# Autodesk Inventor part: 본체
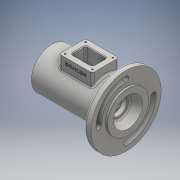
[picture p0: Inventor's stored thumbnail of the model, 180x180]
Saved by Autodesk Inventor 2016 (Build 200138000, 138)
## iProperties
Created: 2017-05
Part Number: 본체
Material: 일반
Document SubType Name: Modeling
Designer: USER
Density: 1 g/cm^3
Appearance: 기본값
Author: USER
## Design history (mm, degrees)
sketch "스케치1"
  geometry: L1 (0, 0)-(0, 31); L2 (0, 31)-(102, 31); L3 (102, 31)-(102, 50); L4 (105, 53)-(112, 53); L5 (112, 53)-(112, 31); L6 (112, 31)-(115, 31); L7 (115, 31)-(115, 0); L8 (115, 0)-(0, 0); L9 (9, 0)-(9, 24); L10 (9, 24)-(12, 24); L11 (12, 24)-(12, 20); L12 (21, 20)-(21, 17.5); L13 (21, 17.5)-(24.25, 17.5); L14 (24.25, 17.5)-(24.25, 18.5); L15 (24.25, 18.5)-(26, 18.5); L16 (26, 18.5)-(26, 17.5); L17 (26, 17.5)-(36, 17.5); L18 (37, 18.5)-(37, 23); L19 (40, 26)-(72, 26); L20 (75, 23)-(75, 18.5); L21 (76, 17.5)-(86, 17.5); L22 (86, 17.5)-(86, 16.5); L23 (12, 20)-(21, 20); L24 (86, 16.5)-(88, 16.5); L25 (91, 13.5)-(91, 10); L26 (91, 10)-(93.7, 10); L27 (93.7, 10)-(93.7, 12.2); L28 (94, 12.5)-(100.3, 12.5); L29 (100.3, 12.5)-(101, 12.904); L30 (101, 12.904)-(101, 14.455); L31 (102.903, 17.248)-(115, 22); L32 (36, 17.5)-(37, 18.5); L33 (76, 17.5)-(75, 18.5); A1 r 3 centre (104, 14.455) between (102.903, 17.248) and (101, 14.455); A2 r 0.3 centre (94, 12.2) between (94, 12.5) and (93.7, 12.2); A3 r 3 centre (88, 13.5) between (91, 13.5) and (88, 16.5); A4 r 3 centre (40, 23) between (40, 26) and (37, 23); A5 r 3 centre (72, 23) between (75, 23) and (72, 26); A6 r 3 centre (105, 50) between (105, 53) and (102, 50); 4 further points
  constraints: 66 end point, 18 perpendicular, 12 point on circle, 12 point on line, 12 tangent, 6 centre point, 5 vertical, 3 equal radius, 3 horizontal
  dimensions: "d0" = 115 distance between parallel lines of L7 L1; "d1" = 3 distance between parallel lines of L7 L5; "d2" = 13 distance between parallel lines of L7 L3; "d3" = 106 diameter of L4 L8; "d4" = 62 diameter of L6 L8; "d5" = 62 diameter of L2 L8; "d7" = 48 diameter of L10 L8; "d10" = 3 distance between parallel lines of L11 L9; "d11" = 12 distance from line of L11.end L1; "d12" = 40 diameter of L23 L8; "d13" = 21 distance between parallel lines of L1 L12; "d14" = 35 diameter of L13 L8; "d15" = 37 diameter of L15 L8; "d16" = 1.75 distance between parallel lines of L16 L14; "d17" = 26 distance between parallel lines of L16 L1; "d18" = 35 diameter of L17 L8; "d19" = 52 diameter of L19 L8; "d20" = 11 distance between parallel lines of L18 L16; "d21" = 11 distance between parallel lines of L22 L20; "d22" = 35 diameter of L21 L8 (derived); "d24" = 38 distance between parallel lines of L20 L18; "d27" = 33 diameter of L24 L8; "d29" = 20 diameter of L26 L8; "d30" = 25 diameter of L28 L8; "d31" = 5 distance of L22.end point (91, 16.5); "d32" = 2.7 distance of L25.end L26.end; "d34" = 0.7 distance from line of L30 L28.end; "d35" = 30 deg angle of L29 L28; "d36" = 44 diameter of L31.end L8; "d37" = 33 diameter of point (101, 16.5) L8; "d38" = 14 distance between parallel lines of L7 L30; "d39" = 3 radius of A1; "d40" = 0.3 radius of A2; "d41" = 1 distance of L17.end point (37, 17.5); "d42" = 1 distance of L18.start point (37, 17.5) (= d41); "d43" = 1 distance of L21.start point (75, 17.5) (= d41); "d44" = 1 distance of L20.end point (75, 17.5) (= d43); "d45" = 3 radius of A6; "d98" = 7.3 distance between parallel lines of L30 L27 (derived)
revolve "회전1" sketch "스케치1" stored, may be unused: angle "d46" = 90 deg
hole "구멍1" diameter "d49" = 40.376; stored, may be unused: countersink angle "d53" = 90 deg, drill point angle "d55" = 0 deg; dims "d47" = 10, "d48" = 10, "d50" = 12, "d51" = 4, "d52" = 2, "d54" = 12
chamfer "모따기1" distance "d56" = 1; stored, may be unused: second distance "d57" = 2, angle "d58" = 45 deg
sketch "스케치2"
  geometry: L1 (0, 37.5)-(0, 45.5); L2 (37.5, 0)-(45.5, 0); L3 (-37.5, 0)-(-45.5, 0); L4 (0, -45.5)-(0, -37.5); C1 r 41.5 at (0, 0); C2 r 53 at (0, 0) reference; A1 r 4 centre (0, 41.5) between (0, 45.5) and (0, 37.5); A2 r 4 centre (41.5, 0) between (37.5, 0) and (45.5, 0); A3 r 4 centre (-41.5, 0) between (-37.5, 0) and (-45.5, 0); A4 r 4 centre (0, -41.5) between (0, -45.5) and (0, -37.5); A5 r 37.5 centre (0, 0) between (-37.5, 0) and (0, -37.5); A6 r 37.5 centre (0, 0) between (37.5, 0) and (0, 37.5); A7 r 45.5 centre (0, 0) between (-45.5, 0) and (0, -45.5); A8 r 45.5 centre (0, 0) between (45.5, 0) and (0, 45.5); 5 further points
  constraints: 16 point on circle, 9 centre point, 8 end point, 7 coincident, 4 midpoint, 2 horizontal alignment, 2 perpendicular, 2 vertical alignment, 1 horizontal, 1 vertical
  dimensions: "d59" = 83 diameter of C1; "d62" = 45.5 radius of A7; "d63" = 37.5 radius of A5; "d64" = 37.5 radius of A6; "d65" = 45.5 radius of A8
extrude "돌출1" cut sketch "스케치2" distance "d66" = 30; taper "d67" = 0 deg
node "작업 평면1"
sketch "스케치3"
  geometry: L1 (31, -20)-(81, -20); L2 (81, -20)-(81, 20); L3 (81, 20)-(31, 20); L4 (31, 20)-(31, -20); 4 further points
  constraints: 8 end point, 2 horizontal alignment, 2 midpoint, 2 parallel, 1 horizontal, 1 perpendicular, 1 vertical alignment
  dimensions: "d69" = 56 distance of point (56, 0) point (0, 0); "d70" = 40 distance of L3.end L1.start; "d71" = 50 distance of L1.start L1.end
extrude "돌출2" join sketch "스케치3" stored distance "d72" = 30; taper "d73" = 0 deg
sketch "스케치4"
  geometry: L1 (40, 11)-(72, 11); L2 (72, 11)-(72, -11); L3 (72, -11)-(40, -11); L4 (40, -11)-(40, 11); L5 (81, 20)-(31, 20) reference; L6 (31, 20)-(31, -20) reference; 5 further points
  constraints: 8 end point, 4 midpoint, 2 parallel, 1 horizontal, 1 horizontal alignment, 1 perpendicular, 1 vertical alignment
  dimensions: "d74" = 32 distance of L2.end L3.end; "d75" = 22 distance of L3.end L1.start
extrude "돌출3" cut sketch "스케치4" distance "d76" = 46; taper "d77" = 0 deg
sketch "스케치5"
  geometry: L1 (35.5, 15.5)-(76.5, 15.5); L2 (76.5, 15.5)-(76.5, -15.5); L3 (76.5, -15.5)-(35.5, -15.5); L4 (35.5, -15.5)-(35.5, 15.5); L5 (40, 11)-(72, 11) reference; L6 (40, -11)-(40, 11) reference; 9 further points
  constraints: 8 end point, 4 coincident, 4 midpoint, 2 parallel, 1 horizontal, 1 horizontal alignment, 1 perpendicular, 1 vertical alignment
  dimensions: "d78" = 41 distance of L2.end L3.end; "d79" = 31 distance of L3.end L1.start
hole "구멍2" sketch "스케치5" at (35.5, 15.5), (35.5, -15.5), (76.5, 15.5), (76.5, -15.5) diameter "d80" = 2.459; stored, may be unused: countersink angle "d84" = 90 deg, drill point angle "d86" = 120 deg; dims "d81" = 6, "d82" = 4, "d83" = 2, "d85" = 8
fillet "모깎기1" dims "d87" = 3
chamfer "모따기2" distance "d88" = 1; stored, may be unused: second distance "d89" = 2, angle "d90" = 45 deg
fillet "모깎기2" dims "d91" = 3
fillet "모깎기3" dims "d92" = 3
node "작업 평면2"
sketch "스케치6"
  geometry: L1 (0, -31)-(0, 31) reference; L2 (34, 44)-(78, 44) reference; 2 further points
  constraints: 1 other
  dimensions: "d94" = 56 distance from line of point (56, 36) L1; "d95" = 8 distance from line of point (56, 36) L2
feature "엠보싱1" sketch "스케치6" dims "d96" = 0.5, "d97" = 0
node "솔리드1"
other parameters: "d60" = 91, "d61" = 75, "d68" = 44
